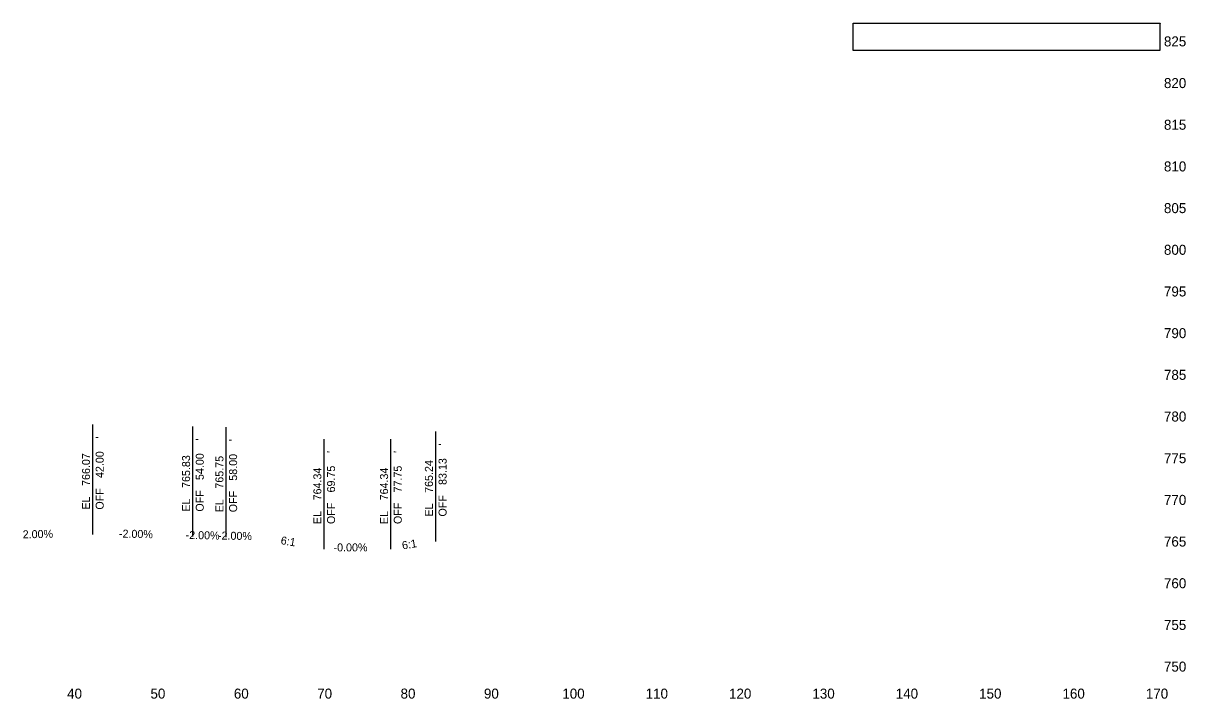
# Model space of a CAD drawing. Extents: x -114 to 173, y 743 to 828.
# Drawn here: x 33.6 to 173.1, y 747 to 828 of the extents above; entities that cross this region are included whole.
import ezdxf

# ---------------------------------------------------------------- set-up
doc = ezdxf.new("R2010")
doc.units = 0
for name, color, linetype in [('Border-Profile bottom shape', 7, 'Continuous'), ('XS-Feature Text', 7, 'Continuous'), ('XS-Segment Text', 7, 'Continuous'), ('XS-Text', 7, 'Continuous')]:
    doc.layers.add(name, color=color, linetype=linetype)

msp = doc.modelspace()

# ---------------------------------------------------------------- linework, layer by layer
at = {"layer": 'Border-Profile bottom shape'}
msp.add_lwpolyline([(133.2, 828.01), (170, 828.01), (170, 824.73), (133.2, 824.73)], close=True, dxfattribs=at)
msp.add_lwpolyline([(133.2, 828.01), (170, 828.01), (170, 824.73), (133.2, 824.73)], close=True, dxfattribs=at)
msp.add_circle((170, 828.01), 0.01, dxfattribs=at)
msp.add_circle((170, 828.01), 0.01, dxfattribs=at)
msp.add_circle((170, 828.01), 0.01, dxfattribs=at)
msp.add_circle((170, 828.01), 0.01, dxfattribs=at)
msp.add_circle((170, 828.01), 0.01, dxfattribs=at)
msp.add_circle((170, 828.01), 0.01, dxfattribs=at)
msp.add_circle((170, 828.01), 0.01, dxfattribs=at)
msp.add_circle((170, 828.01), 0.01, dxfattribs=at)
msp.add_circle((170, 828.01), 0.01, dxfattribs=at)
msp.add_circle((170, 828.01), 0.01, dxfattribs=at)
msp.add_circle((170, 828.01), 0.01, dxfattribs=at)
msp.add_circle((170, 828.01), 0.01, dxfattribs=at)
at = {"layer": 'XS-Feature Text'}
for p, q in [((42, 766.67), (42, 779.87)), ((54, 766.43), (54, 779.63)), ((58, 766.35), (58, 779.55)), ((69.75, 764.94), (69.75, 778.14)), ((77.75, 764.94), (77.75, 778.14)), ((83.13, 765.84), (83.13, 779.04))]:
    msp.add_line(p, q, dxfattribs=at)

# ---------------------------------------------------------------- texts
for s, p in [("'", (43.3, 778.2)), ("'", (55.3, 777.96)), ("'", (59.3, 777.88)), ("'", (84.43, 777.36)), ('766.07', (41.66, 772.51)), ('42.00', (43.3, 773.46)), ('765.83', (53.66, 772.27)), ('54.00', (55.3, 773.22)), ('765.75', (57.66, 772.19)), ('58.00', (59.3, 773.14)), ("'", (71.05, 776.47)), ("'", (79.05, 776.47)), ('765.24', (82.79, 771.68)), ('83.13', (84.43, 772.63)), ('764.34', (69.41, 770.78)), ('69.75', (71.05, 771.73)), ('764.34', (77.41, 770.78)), ('77.75', (79.05, 771.73)), ('EL ', (41.66, 769.67)), ('OFF ', (43.3, 769.67)), ('OFF ', (55.3, 769.43)), ('OFF ', (59.3, 769.35)), ('OFF ', (84.43, 768.84)), ('EL ', (53.66, 769.43)), ('EL ', (57.66, 769.35)), ('OFF ', (71.05, 767.94)), ('OFF ', (79.05, 767.94)), ('EL ', (82.79, 768.84)), ('EL ', (69.41, 767.94)), ('EL ', (77.41, 767.94))]:
    msp.add_text(s, height=0.96, rotation=90, dxfattribs=at).set_placement(p)
at = {"layer": 'XS-Segment Text'}
for s, rotation, p in [('2.00%', 1.1458, (33.59, 766.22)), ('-2.00%', 358.8542, (45.12, 766.32)), ('-2.00%', 358.8542, (53.12, 766.16)), ('-2.00%', 358.8542, (57, 766.09)), ('6:1', 350.5375, (64.48, 765.54)), ('-0.00%', 360, (70.87, 764.66)), ('6:1', 9.4625, (79.16, 764.89))]:
    msp.add_text(s, height=0.96, rotation=rotation, dxfattribs=at).set_placement(p)
at = {"layer": 'XS-Text'}
for s, p in [('825', (170.48, 825.24)), ('820', (170.48, 820.24)), ('815', (170.48, 815.24)), ('810', (170.48, 810.24)), ('805', (170.48, 805.24)), ('800', (170.48, 800.24)), ('795', (170.48, 795.24)), ('790', (170.48, 790.24)), ('785', (170.48, 785.24)), ('780', (170.48, 780.24)), ('775', (170.48, 775.24)), ('770', (170.48, 770.24)), ('765', (170.48, 765.24)), ('760', (170.48, 760.24)), ('755', (170.48, 755.24)), ('750', (170.48, 750.24)), ('40', (38.91, 747)), ('50', (48.91, 747)), ('60', (58.91, 747)), ('70', (68.91, 747)), ('80', (78.91, 747)), ('90', (88.91, 747)), ('100', (98.31, 747)), ('110', (108.31, 747)), ('120', (118.31, 747)), ('130', (128.31, 747)), ('140', (138.31, 747)), ('150', (148.31, 747)), ('160', (158.31, 747)), ('170', (168.31, 747))]:
    msp.add_text(s, height=1.2, dxfattribs=at).set_placement(p)

doc.saveas('drawing.dxf')
